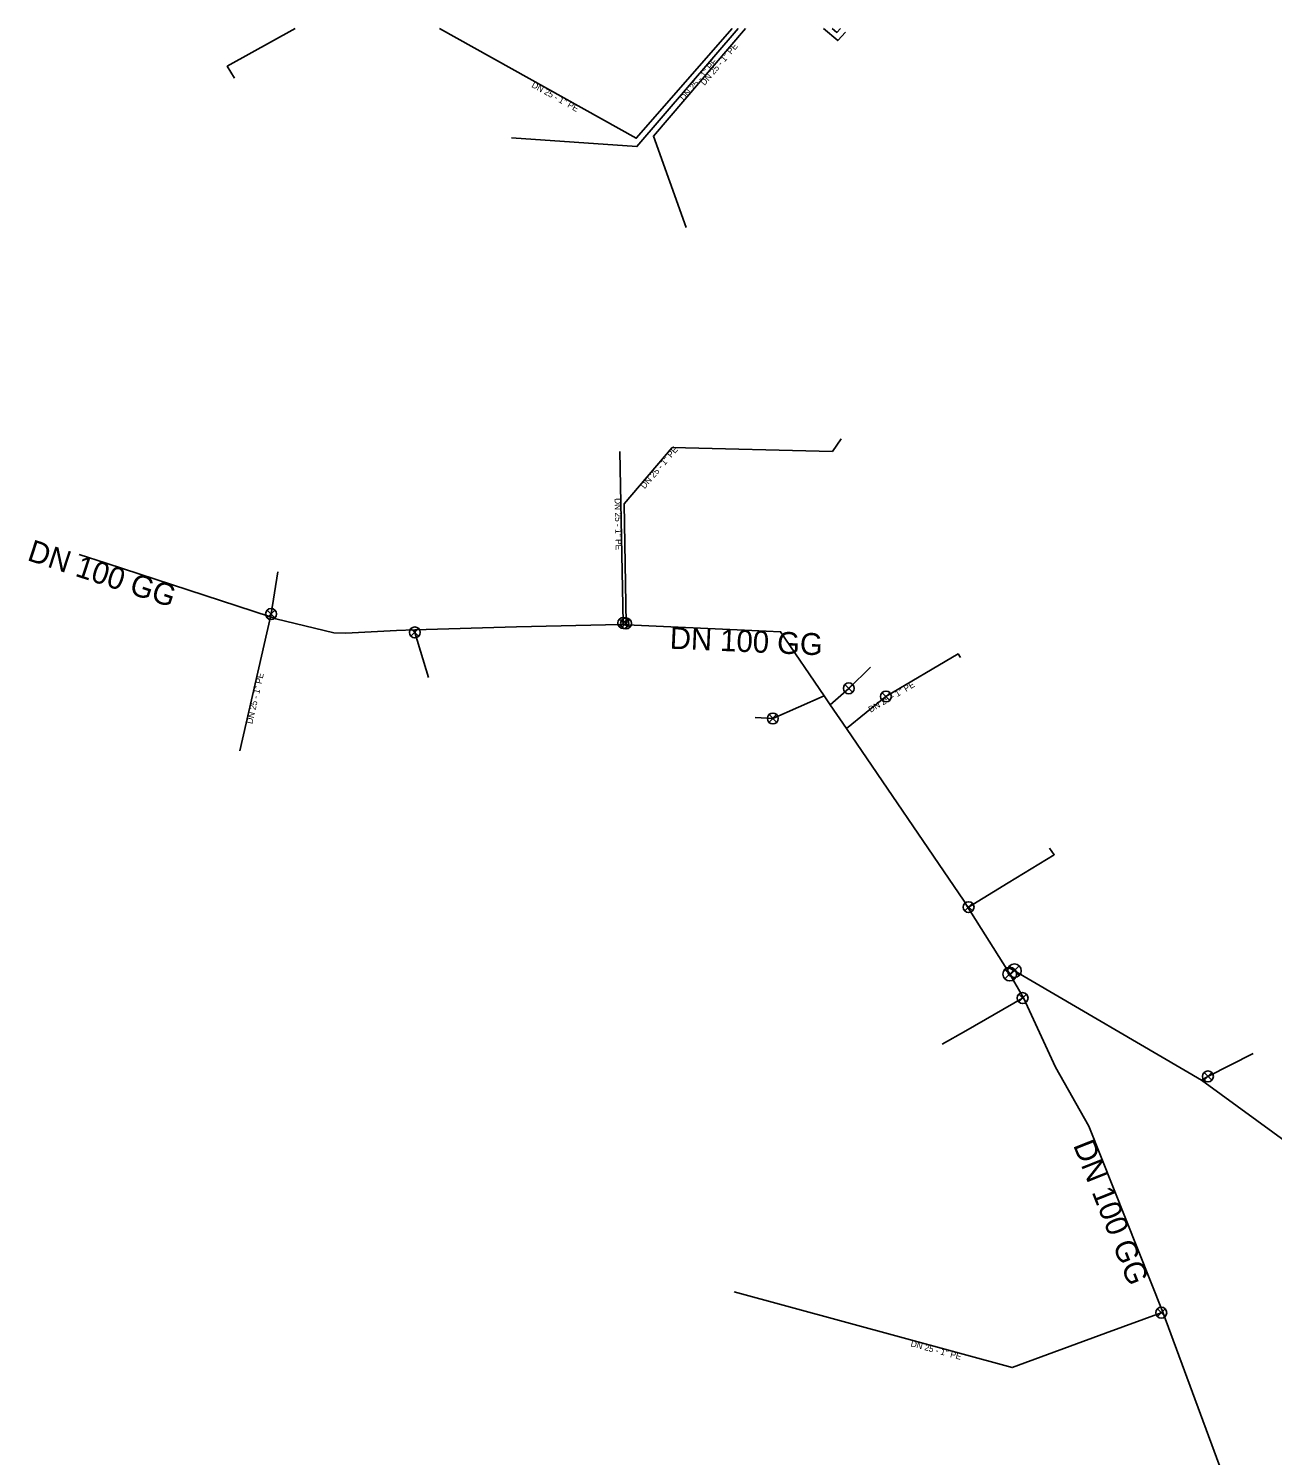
# Model space of a CAD drawing. Extents: x -484784 to -484458, y -1128042 to -1127614.
# Drawn here: x -484784.4 to -484693.2, y -1127718.4 to -1127613.8 of the extents above; entities that cross this region are included whole.
import ezdxf

# ---------------------------------------------------------------- set-up
doc = ezdxf.new("R2010")
doc.units = 0
for name, color, linetype in [('_pripojka_prevzato_z_dokumentace_', 7, 'Continuous'), ('_pripojka_priblizne_', 7, 'Continuous'), ('_voda_smvak_prevzato_z_dokumentace_', 7, 'Continuous'), ('Default', 7, 'Continuous'), ('MoLevel 27', 7, 'Continuous'), ('MoLevel 32', 7, 'Continuous'), ('MoLevel 46', 7, 'Continuous'), ('MoLevel 53', 7, 'Continuous'), ('MoLevel 55', 7, 'Continuous')]:
    doc.layers.add(name, color=color, linetype=linetype)

# ---------------------------------------------------------------- blocks, each defined once
blk = doc.blocks.new('_uzaver_')
at = {"layer": 'Default'}
for p, q in [((-0.000035, -0.000035), (0.000035, 0.000035)), ((0.000035, -0.000035), (-0.000035, 0.000035))]:
    blk.add_line(p, q, dxfattribs=at)
for radius in [0.00005, 0.0000025]:
    blk.add_circle((0, 0), radius, dxfattribs=at)
blk = doc.blocks.new('_uzaver_pripojka_')
at = {"layer": 'Default'}
for p, q in [((-0.000035, -0.000035), (0.000035, 0.000035)), ((0.000035, -0.000035), (-0.000035, 0.000035))]:
    blk.add_line(p, q, dxfattribs=at)
for radius in [0.00005, 0.0000025]:
    blk.add_circle((0, 0), radius, dxfattribs=at)

msp = doc.modelspace()

# ---------------------------------------------------------------- linework, layer by layer
at = {"layer": '_pripojka_prevzato_z_dokumentace_'}
for p, q in [((-484768.88, -1127666.75), (-484766.64, -1127656.92)), ((-484715.67, -1127687.26), (-484717.4, -1127688.25))]:
    msp.add_line(p, q, dxfattribs=at)
for points in [[(-484766.64, -1127656.92), (-484766.6, -1127656.71), (-484766.11, -1127653.63)], [(-484756.06, -1127657.87), (-484756.06, -1127658.06), (-484755.06, -1127661.37)], [(-484725.6, -1127663.36), (-484724.24, -1127662.16), (-484722.65, -1127660.61)], [(-484731.11, -1127664.31), (-484729.81, -1127664.37), (-484726.04, -1127662.72)], [(-484711.43, -1127684.86), (-484711.5, -1127684.87), (-484715.67, -1127687.26)], [(-484698.39, -1127690.88), (-484697.91, -1127690.61), (-484694.59, -1127688.94)]]:
    msp.add_lwpolyline(points, dxfattribs=at)
at = {"layer": '_pripojka_priblizne_'}
msp.add_line((-484724.41, -1127665.1), (-484721.52, -1127662.76), dxfattribs=at)
for points in [[(-484764.83, -1127613.79), (-484769.81, -1127616.55), (-484769.27, -1127617.42)], [(-484732.79, -1127613.79), (-484739.82, -1127621.83), (-484754.26, -1127613.79)], [(-484732.34, -1127613.79), (-484739.77, -1127622.45), (-484748.97, -1127621.8)], [(-484731.82, -1127613.79), (-484738.57, -1127621.68), (-484736.16, -1127628.37)], [(-484724.48, -1127614.06), (-484725.05, -1127614.68), (-484726.1, -1127613.79)], [(-484724.86, -1127613.79), (-484725.11, -1127614.07), (-484725.46, -1127613.79)], [(-484740.51, -1127657.51), (-484740.57, -1127657.4), (-484740.72, -1127648.63), (-484737.19, -1127644.5), (-484725.44, -1127644.81), (-484724.79, -1127643.86)], [(-484740.79, -1127657.49), (-484740.78, -1127657.37), (-484741.02, -1127644.79)], [(-484721.52, -1127662.76), (-484716.23, -1127659.64), (-484716.06, -1127659.9)], [(-484712.55, -1127676.42), (-484709.18, -1127674.36), (-484709.52, -1127673.88)], [(-484715.53, -1127678.19), (-484715.46, -1127678.2), (-484712.55, -1127676.42)], [(-484705.42, -1127709.43), (-484712.27, -1127711.95), (-484732.65, -1127706.41)], [(-484701.22, -1127707.9), (-484701.33, -1127707.93), (-484705.42, -1127709.43)]]:
    msp.add_lwpolyline(points, dxfattribs=at)
at = {"layer": '_voda_smvak_prevzato_z_dokumentace_'}
msp.add_line((-484712.44, -1127683.11), (-484712.65, -1127682.74), dxfattribs=at)
for points in [[(-484761.11, -1127658.11), (-484762, -1127658.09), (-484766.24, -1127657.06), (-484766.64, -1127656.92), (-484778.69, -1127652.98), (-484780.67, -1127652.36)], [(-484712.65, -1127682.74), (-484715.53, -1127678.19), (-484715.77, -1127677.76), (-484724.41, -1127665.1), (-484725.6, -1127663.36), (-484726.04, -1127662.72), (-484729.24, -1127658.01), (-484731.35, -1127657.91), (-484740.51, -1127657.51), (-484740.79, -1127657.49), (-484740.99, -1127657.48), (-484748.6, -1127657.66), (-484756.06, -1127657.87), (-484757.41, -1127657.91), (-484761.11, -1127658.11)], [(-484712.1, -1127682.86), (-484712.46, -1127682.68), (-484712.65, -1127682.74)], [(-484643.08, -1127765.34), (-484645.56, -1127761.38), (-484646.12, -1127760.52), (-484650.61, -1127753.6), (-484650.95, -1127753.11), (-484652.74, -1127750.29), (-484654.58, -1127747.8), (-484659.5, -1127741.98), (-484663.3, -1127738.25), (-484667.45, -1127734.47), (-484668.22, -1127733.67), (-484673.26, -1127728.1), (-484673.76, -1127727.55), (-484675.04, -1127726.21), (-484681.24, -1127716.17), (-484682.76, -1127712.65), (-484683.58, -1127711.28), (-484684.33, -1127709.73), (-484687.86, -1127701.92), (-484687.92, -1127701.76), (-484691.71, -1127695.75), (-484698.39, -1127690.88), (-484712.1, -1127682.86)], [(-484696.15, -1127721.64), (-484696.87, -1127719.68), (-484701.22, -1127707.9), (-484706.63, -1127694.26), (-484709.08, -1127689.93), (-484711.43, -1127684.86), (-484712.44, -1127683.11)]]:
    msp.add_lwpolyline(points, dxfattribs=at)

# ---------------------------------------------------------------- block references
at = {"layer": 'MoLevel 27', "xscale": 10000, "yscale": 10000}
for p in [(-484712.44, -1127683.11), (-484712.1, -1127682.86)]:
    msp.add_blockref('_uzaver_', p, dxfattribs=at)
at = {"layer": 'MoLevel 53', "xscale": 7999.999999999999, "yscale": 7999.999999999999}
for p in [(-484766.6, -1127656.71), (-484756.06, -1127658.06), (-484740.78, -1127657.37), (-484740.57, -1127657.4), (-484724.24, -1127662.16), (-484721.52, -1127662.76), (-484729.81, -1127664.37), (-484715.46, -1127678.2), (-484711.5, -1127684.87), (-484697.91, -1127690.61), (-484701.33, -1127707.93)]:
    msp.add_blockref('_uzaver_pripojka_', p, dxfattribs=at)

# ---------------------------------------------------------------- texts
at = {"layer": 'MoLevel 32'}
for rotation, p in [(49.445, (-484734.82, -1127618)), (49.3739, (-484736.31, -1127619.13)), (330.8877, (-484747.54, -1127618.06)), (49.4296, (-484739.21, -1127647.57)), (271.0751, (-484741.41, -1127648.22)), (30.5299, (-484722.64, -1127663.95)), (344.8049, (-484719.74, -1127710.39))]:
    msp.add_text("DN 25 - 1'' PE", height=0.455, rotation=rotation, dxfattribs=at).set_placement(p)
at = {"layer": 'MoLevel 46'}
for rotation, p in [(341.8766, (-484784.55, -1127652.75)), (357.4504, (-484737.39, -1127659.25)), (291.6266, (-484707.81, -1127695.64))]:
    msp.add_text('DN 100 GG', height=1.605, rotation=rotation, dxfattribs=at).set_placement(p)
at = {"layer": 'MoLevel 55'}
msp.add_text("DN 25 - 1'' PE", height=0.455, rotation=77.1703, dxfattribs=at).set_placement((-484767.97, -1127664.8))

doc.saveas('drawing.dxf')
